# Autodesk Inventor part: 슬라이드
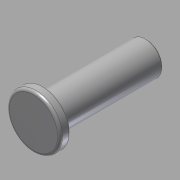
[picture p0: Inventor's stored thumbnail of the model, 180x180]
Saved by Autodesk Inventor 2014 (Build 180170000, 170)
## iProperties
Company: 한국ATC센터
Created: 2015-11
Part Number: 슬라이드
Document SubType Name: Modeling
Designer: mdu
Density: 7.86 g/cm^3
Material: 강철, 연강
Mass: 53.476 g
Surface Area: 25.6477 cm^2
Volume: 6.80356 cm^3
Appearance: 강철
Author: mdu
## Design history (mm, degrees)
sketch "스케치1"
  geometry: L1 (13.5, 41)-(13.5, 74) reference; L2 (13.5, 74)-(26.5, 74) reference; L3 (20, 74)-(20, 29); L4 (20, 74)-(13.5, 74); L5 (13.5, 74)-(13.5, 33); L6 (13.5, 33)-(9.5, 33); L7 (9.5, 33)-(9.5, 29); L8 (20, 73.5)-(13.5, 73.5); L9 (20, 29)-(9.5, 29); 1 further point
  constraints: 16 end point, 4 perpendicular, 3 point on line, 1 collinear, 1 midpoint, 1 parallel, 1 vertical, 2 other
  dimensions: "d0" = 45 distance of L3.start L3.end; "d1" = 21 diameter of L7 L3; "d2" = 4 distance from line of L3.end L6; "d4" = 0.5 distance between parallel lines of L8 L2
revolve "회전1" sketch "스케치1" stored, may be unused: angle "d5" = 90 deg
fillet "모깎기1" dims "d6" = 1
fillet "모깎기3" dims "d8" = 0.5
chamfer "모따기1" distance "d9" = 0.5; stored, may be unused: second distance "d10" = 2, angle "d11" = 45 deg
sketch "스케치2"
  geometry: C1 r 6.5 at (0, 0) reference; C2 r 7.25 at (0, 0); 1 further point
  constraints: 1 centre point, 1 coincident
  dimensions: "d12" = 14.5 diameter of C2
extrude "돌출1" join sketch "스케치2" distance "d13" = 2; taper "d14" = 0 deg
node "솔리드1"
node "참조1"
